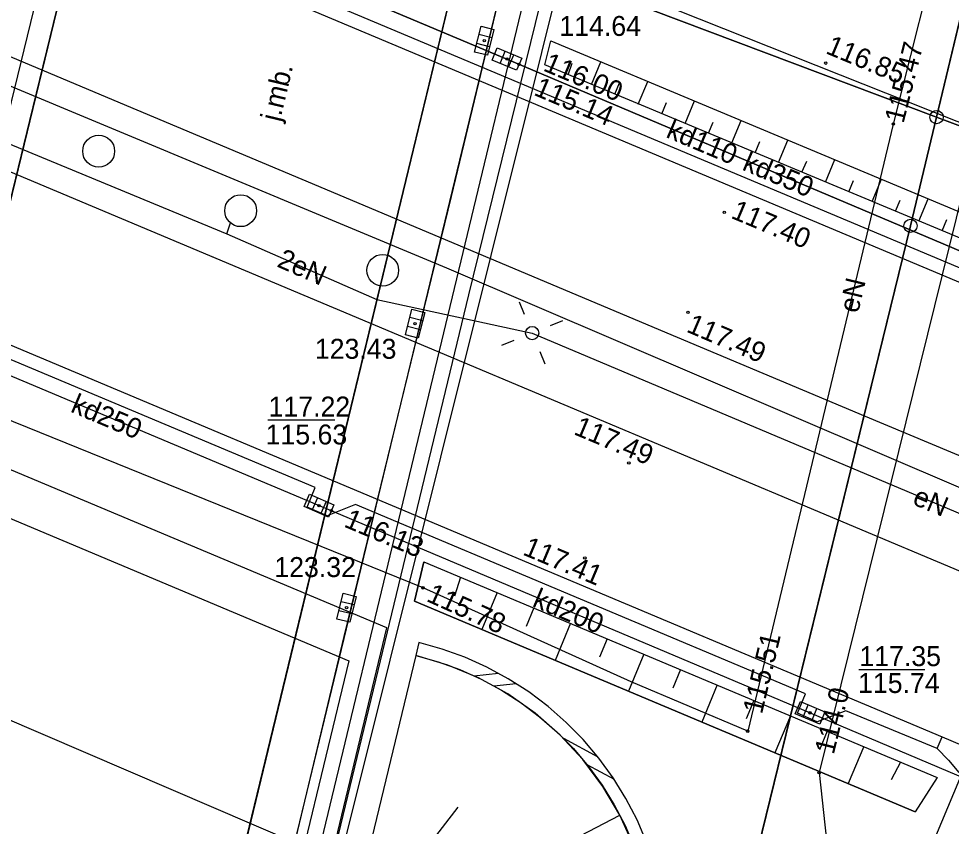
# Model space of a CAD drawing. Extents: x 6424617 to 6425697, y 5665845 to 5667190.
# Drawn here: x 6425461.6 to 6425496.67, y 5666928.18 to 5666958.55 of the extents above; entities that cross this region are included whole.
import ezdxf

# ---------------------------------------------------------------- set-up
doc = ezdxf.new("R2010")
doc.units = 0
for name, color, linetype in [('Warstwa 1', 7, 'Continuous'), ('Warstwa 10', 7, 'Continuous'), ('Warstwa 12', 7, 'Continuous'), ('Warstwa 13', 7, 'Continuous'), ('Warstwa 14', 7, 'Continuous'), ('Warstwa 15', 7, 'Continuous'), ('Warstwa 16', 7, 'Continuous'), ('Warstwa 2', 7, 'Continuous'), ('Warstwa 20', 7, 'Continuous'), ('Warstwa 21', 7, 'Continuous'), ('Warstwa 25', 7, 'Continuous'), ('Warstwa 4', 7, 'Continuous'), ('Warstwa 6', 7, 'Continuous'), ('Warstwa 8', 7, 'Continuous'), ('Warstwa 9', 7, 'Continuous')]:
    doc.layers.add(name, color=color, linetype=linetype)

msp = doc.modelspace()

# ---------------------------------------------------------------- linework, layer by layer
at = {"layer": 'Warstwa 1'}
for p, q in [((6425437.407, 5666792.342), (6425493.084, 5667022.41)), ((6425437.407, 5666792.342), (6425493.084, 5667022.41)), ((6425496.12, 5666954.85), (6425511.35, 5667018.315)), ((6425496.12, 5666954.85), (6425511.35, 5667018.315)), ((6425485.36, 5666958.9), (6425496.12, 5666954.85)), ((6425485.36, 5666958.9), (6425496.12, 5666954.85)), ((6425495.139, 5666950.762), (6425496.12, 5666954.85)), ((6425495.139, 5666950.762), (6425496.12, 5666954.85)), ((6425496.12, 5666954.85), (6425522.252, 5666945.035)), ((6425496.12, 5666954.85), (6425522.252, 5666945.035)), ((6425471.236, 5666853.116), (6425495.139, 5666950.762)), ((6425471.236, 5666853.116), (6425495.139, 5666950.762))]:
    msp.add_line(p, q, dxfattribs=at)
msp.add_lwpolyline([(6425437.93, 5666938.04), (6425438.42, 5666937.92), (6425439.31, 5666941.59), (6425439.89, 5666941.44), (6425441.5, 5666948.08), (6425474.02, 5666934.4), (6425472.29, 5666927.24), (6425472.87, 5666927.1), (6425472.03, 5666923.61), (6425472.52, 5666923.49), (6425475.45, 5666935.64), (6425458.58, 5666942.73), (6425458.34, 5666941.75), (6425456.1, 5666942.69), (6425456.34, 5666943.68), (6425440.88, 5666950.18)], close=True, dxfattribs=at)
for centre, radius in [((6425464.61, 5666953.57), 0.601), ((6425469.95, 5666951.33), 0.6), ((6425475.29, 5666949.09), 0.599)]:
    msp.add_circle(centre, radius, dxfattribs=at)
at = {"layer": 'Warstwa 10'}
for points in [[(6425485.214, 5666927.589), (6425484.855, 5666928.426), (6425484.434, 5666929.234), (6425483.955, 5666930.009), (6425483.42, 5666930.746), (6425482.831, 5666931.441), (6425482.192, 5666932.09), (6425481.507, 5666932.69), (6425480.78, 5666933.238), (6425480.013, 5666933.73), (6425479.212, 5666934.164), (6425478.381, 5666934.537), (6425477.525, 5666934.847), (6425476.648, 5666935.093), (6425476.532, 5666934.607), (6425477.372, 5666934.371), (6425478.194, 5666934.073), (6425478.991, 5666933.715), (6425479.759, 5666933.299), (6425480.494, 5666932.827), (6425481.192, 5666932.302), (6425481.849, 5666931.726), (6425482.462, 5666931.104), (6425483.026, 5666930.437), (6425483.54, 5666929.73), (6425483.999, 5666928.987), (6425484.403, 5666928.212), (6425484.747, 5666927.409)], [(6425478.72, 5666933.845), (6425479.647, 5666933.938)], [(6425479.465, 5666933.468), (6425480.306, 5666933.552)], [(6425482.086, 5666931.497), (6425483.379, 5666930.797)], [(6425482.973, 5666930.506), (6425483.992, 5666929.954)]]:
    msp.add_lwpolyline(points, dxfattribs=at)
for centre in [(6425496.12, 5666954.85), (6425496.12, 5666954.85), (6425495.139, 5666950.762), (6425495.139, 5666950.762)]:
    msp.add_circle(centre, 0.25, dxfattribs=at)
at = {"layer": 'Warstwa 12'}
for points in [[(6425454.75, 5666812.915), (6425455.753, 5666816.883), (6425457.009, 5666817.738), (6425466.513, 5666831.046), (6425477.951, 5666845.959), (6425477.163, 5666847.339), (6425475.812, 5666851.526), (6425475.173, 5666855.074), (6425474.407, 5666861.19), (6425474.538, 5666868.989), (6425475.24, 5666876.27), (6425477.752, 5666888.602), (6425479.441, 5666893.041), (6425480.828, 5666893.587), (6425484.849, 5666908.144), (6425470.76, 5666912.634), (6425469.827, 5666913.063), (6425472.078, 5666923.598), (6425472.03, 5666923.61), (6425482.03, 5666965.191), (6425489.31, 5666994.281), (6425496.49, 5667021.647)], [(6425470.675, 5666812.723), (6425472.304, 5666820.347), (6425476.107, 5666835.553), (6425479.576, 5666850.831), (6425493.276, 5666901.432), (6425493.535, 5666902.072), (6425493.16, 5666902.53), (6425486.027, 5666904.729), (6425481.07, 5666906.403), (6425469.466, 5666909.139), (6425469.101, 5666909.586), (6425469.483, 5666910.214), (6425471.98, 5666923.618), (6425472.03, 5666923.61), (6425482.03, 5666965.191), (6425489.31, 5666994.281), (6425496.49, 5667021.647)], [(6425438.44, 5666974.48), (6425442.87, 5666972.63), (6425461.54, 5666964.77), (6425479.96, 5666957.03), (6425498.41, 5666949.22), (6425503.59, 5666947.03), (6425504.05, 5666946.83)], [(6425504.05, 5666946.83), (6425503.59, 5666947.03), (6425498.41, 5666949.22), (6425479.96, 5666957.03), (6425461.54, 5666964.77), (6425442.87, 5666972.63), (6425438.44, 5666974.48)], [(6425553.71, 5666947.2), (6425549.6, 5666948.95), (6425497.24, 5666962.99), (6425496.43, 5666962.29), (6425494.49, 5666954.59), (6425489.02, 5666931.76), (6425484.64, 5666933.61), (6425476.81, 5666937.15), (6425438.84, 5666952.53), (6425435.57, 5666952.21), (6425429.97, 5666954.78), (6425402.11, 5666966.81), (6425387.27, 5666972.4), (6425380.77, 5666966.54), (6425363.64, 5666950.72), (6425363.13, 5666950.36), (6425362.37, 5666949.84), (6425357.72, 5666956.9), (6425346.14, 5666972.82)], [(6425526.974, 5666967.965), (6425526.723, 5666966.717), (6425523.453, 5666965.476), (6425499.982, 5666962.636), (6425499.521, 5666962.359), (6425497.672, 5666954.347), (6425491.703, 5666930.204), (6425491.983, 5666927.664), (6425491.536, 5666926.843), (6425491.124, 5666926.349), (6425486.048, 5666904.094), (6425485.647, 5666901.708), (6425484.933, 5666901.883), (6425464.654, 5666907.42), (6425437.078, 5666914.799)], [(6425435.28, 5666966.88), (6425435.74, 5666966.68), (6425477.69, 5666949.18), (6425500.42, 5666939.46), (6425500.88, 5666939.27)], [(6425436.62, 5666965.4), (6425444.74, 5666960.59), (6425451.33, 5666957.94), (6425469.43, 5666950.46), (6425475.07, 5666947.99), (6425480.91, 5666946.73)], [(6425429.54, 5666958.45), (6425436.02, 5666955.7), (6425454.47, 5666947.99), (6425472.9, 5666940.24)], [(6425469.43, 5666950.46), (6425469.566, 5666950.869)], [(6425480.91, 5666946.73), (6425514.86, 5666932.41), (6425528.46, 5666925.91), (6425545.47, 5666915.06), (6425553.34, 5666907.03), (6425561.44, 5666895.63), (6425564.087, 5666890.255)], [(6425472.9, 5666940.24), (6425491.36, 5666932.45)], [(6425500.88, 5666939.27), (6425494.44, 5666923.88), (6425494.89, 5666923.67), (6425515.65, 5666913.94), (6425516.1, 5666913.73), (6425516.07, 5666913.22), (6425516.03, 5666898.31)], [(6425491.36, 5666932.45), (6425509.53, 5666924.76)]]:
    msp.add_lwpolyline(points, dxfattribs=at)
at = {"layer": 'Warstwa 14'}
for p, q in [((6425473.49, 5666943.459), (6425470.977, 5666943.459)), ((6425495.68, 5666934.072), (6425493.201, 5666934.072))]:
    msp.add_line(p, q, dxfattribs=at)
for centre in [(6425479.11, 5666957.72), (6425479.96, 5666957.03), (6425480.42, 5666956.835), (6425480.42, 5666956.835), (6425494.49, 5666954.59), (6425476.51, 5666947.08), (6425472.9, 5666940.24), (6425473.361, 5666940.046), (6425476.81, 5666937.15), (6425473.93, 5666936.4), (6425491.36, 5666932.45), (6425489.02, 5666931.76), (6425491.703, 5666930.204)]:
    msp.add_circle(centre, 0.045, dxfattribs=at)
at = {"layer": 'Warstwa 16'}
msp.add_lwpolyline([(6425473.666, 5666926.849), (6425456.184, 5666934.35), (6425458.05, 5666942), (6425464.35, 5666967.83), (6425465.856, 5666974.004), (6425483.16, 5666964.87)], close=True, dxfattribs=at)
at = {"layer": 'Warstwa 2'}
for points in [[(6425482.64, 5666964.96), (6425478.52, 5666948.17), (6425472.56, 5666923.5)], [(6425569.428, 5666914.078), (6425559.167, 5666924.494), (6425550.651, 5666930.93), (6425537.233, 5666937.954), (6425528.275, 5666942.097), (6425504.759, 5666951.565), (6425481.965, 5666960.63)]]:
    msp.add_lwpolyline(points, dxfattribs=at)
msp.add_circle((6425480.91, 5666946.73), 0.25, dxfattribs=at)
at = {"layer": 'Warstwa 20'}
for points in [[(6425507.766, 5666945.809), (6425481.386, 5666956.809)], [(6425476.843, 5666938.133), (6425496.143, 5666930.021)]]:
    msp.add_lwpolyline(points, dxfattribs=at)
at = {"layer": 'Warstwa 21'}
for points in [[(6425481.612, 5666957.715), (6425506.532, 5666947.292), (6425509.043, 5666948.427)], [(6425476.484, 5666936.646), (6425495.319, 5666928.728)], [(6425477.76, 5666897.255), (6425484.833, 5666917.264), (6425484.95, 5666918.78), (6425484.717, 5666918.871), (6425485.114, 5666920.062), (6425485.382, 5666921.289), (6425485.517, 5666922.537), (6425485.519, 5666923.793), (6425485.386, 5666925.041), (6425485.122, 5666926.268), (6425484.727, 5666927.46), (6425484.208, 5666928.604), (6425483.57, 5666929.685), (6425482.82, 5666930.692), (6425481.968, 5666931.613), (6425481.021, 5666932.438), (6425479.992, 5666933.158), (6425478.892, 5666933.763), (6425477.734, 5666934.248), (6425476.531, 5666934.607)]]:
    msp.add_lwpolyline(points, dxfattribs=at)
at = {"layer": 'Warstwa 25'}
for centre in [(6425491.951, 5666956.878), (6425488.137, 5666951.268), (6425486.77, 5666947.508), (6425484.547, 5666941.847), (6425482.892, 5666938.275)]:
    msp.add_circle(centre, 0.045, dxfattribs=at)
at = {"layer": 'Warstwa 4'}
for p, q in [((6425479.395, 5666957.828), (6425478.911, 5666957.951)), ((6425479.309, 5666957.489), (6425478.825, 5666957.612)), ((6425479.703, 5666956.866), (6425479.893, 5666957.328)), ((6425480.027, 5666956.732), (6425480.217, 5666957.194)), ((6425476.796, 5666947.188), (6425476.311, 5666947.311)), ((6425476.709, 5666946.849), (6425476.224, 5666946.972)), ((6425472.841, 5666940.539), (6425472.639, 5666940.082)), ((6425473.161, 5666940.398), (6425472.959, 5666939.941)), ((6425474.214, 5666936.512), (6425473.727, 5666936.628)), ((6425474.133, 5666936.172), (6425473.646, 5666936.288)), ((6425491.101, 5666932.288), (6425491.296, 5666932.748)), ((6425491.424, 5666932.152), (6425491.619, 5666932.612))]:
    msp.add_line(p, q, dxfattribs=at)
for points in [[(6425479.475, 5666958.143), (6425479.229, 5666957.174), (6425478.745, 5666957.297), (6425478.991, 5666958.266)], [(6425480.327, 5666956.608), (6425479.402, 5666956.989), (6425479.593, 5666957.452), (6425480.518, 5666957.071)], [(6425476.876, 5666947.502), (6425476.628, 5666946.534), (6425476.144, 5666946.658), (6425476.392, 5666947.626)], [(6425472.543, 5666940.671), (6425473.458, 5666940.267), (6425473.257, 5666939.809), (6425472.342, 5666940.213)], [(6425474.289, 5666936.828), (6425474.057, 5666935.856), (6425473.571, 5666935.972), (6425473.803, 5666936.944)], [(6425491.723, 5666932.025), (6425490.802, 5666932.414), (6425490.997, 5666932.875), (6425491.918, 5666932.486)]]:
    msp.add_lwpolyline(points, close=True, dxfattribs=at)
for points in [[(6425480.626, 5666947.424), (6425480.437, 5666947.887)], [(6425481.604, 5666947.014), (6425482.067, 5666947.203)], [(6425480.216, 5666946.446), (6425479.753, 5666946.257)], [(6425481.194, 5666946.036), (6425481.383, 5666945.573)]]:
    msp.add_lwpolyline(points, dxfattribs=at)
at = {"layer": 'Warstwa 6'}
for points in [[(6425493.084, 5667022.41), (6425437.407, 5666792.342), (6425392.62, 5666819.33), (6425356.96, 5666840.82), (6425364.08, 5666857.99), (6425325.81, 5666937.38), (6425352.9, 5666950.36), (6425340.11, 5666976.98), (6425316.39, 5667007.21), (6425286.52, 5667014.65), (6425266.76, 5667059.81), (6425269.791, 5667072.474)], [(6425493.084, 5667022.41), (6425437.407, 5666792.342), (6425454.155, 5666782.149), (6425471.236, 5666853.116), (6425495.139, 5666950.762), (6425496.12, 5666954.85), (6425485.36, 5666958.9), (6425501.348, 5667020.558)], [(6425465.459, 5666899.926), (6425466.149, 5666902.821), (6425466.855, 5666905.711), (6425467.577, 5666908.598), (6425468.314, 5666911.481), (6425468.652, 5666911.404), (6425468.837, 5666912.201), (6425468.584, 5666912.605), (6425468.79, 5666914.12), (6425470.47, 5666921.31), (6425471.24, 5666921.52), (6425471.39, 5666922.11), (6425470.8, 5666922.6), (6425471.1, 5666923.83), (6425473.84, 5666935.32), (6425477.88, 5666951.86), (6425480.16, 5666961.37), (6425481.19, 5666965.36), (6425488.69, 5666995.25), (6425495.536, 5667021.861)], [(6425511.35, 5667018.315), (6425496.12, 5666954.85), (6425485.36, 5666958.9), (6425501.348, 5667020.558)], [(6425511.35, 5667018.315), (6425496.12, 5666954.85), (6425522.252, 5666945.035), (6425525.198, 5666957.05), (6425527.303, 5666965.745), (6425538.589, 5667012.208)], [(6425467.43, 5666976.75), (6425465.18, 5666967.73), (6425462.01, 5666954.72), (6425458.83, 5666941.66), (6425456.77, 5666933.14)], [(6425445.646, 5666970.749), (6425497.767, 5666948.85), (6425498.132, 5666949.624), (6425498.866, 5666949.291), (6425499.296, 5666948.203), (6425507.378, 5666944.806), (6425507.179, 5666944.349)], [(6425474.6, 5666748.65), (6425522.252, 5666945.035), (6425496.12, 5666954.85), (6425495.139, 5666950.762), (6425471.236, 5666853.116), (6425454.155, 5666782.149)], [(6425496.14, 5666931.11), (6425492.711, 5666932.526), (6425491.633, 5666932.106), (6425490.889, 5666932.439), (6425491.192, 5666933.164), (6425474.265, 5666940.282), (6425473.197, 5666939.861), (6425472.453, 5666940.185), (6425472.746, 5666940.92), (6425455.819, 5666948.027)]]:
    msp.add_lwpolyline(points, dxfattribs=at)
at = {"layer": 'Warstwa 8'}
for p, q in [((6425456.98, 5666934.008), (6425466.642, 5666973.589)), ((6425401.285, 5666971.5), (6425496.325, 5666931.551)), ((6425445.458, 5666970.292), (6425507.179, 5666944.349)), ((6425471.991, 5666927.568), (6425480.16, 5666961.37)), ((6425443.04, 5666960.462), (6425476.973, 5666946.195)), ((6425458.123, 5666958.452), (6425465.184, 5666955.484)), ((6425465.184, 5666955.484), (6425472.246, 5666952.516)), ((6425472.246, 5666952.516), (6425479.307, 5666949.548)), ((6425479.307, 5666949.548), (6425486.368, 5666946.579)), ((6425486.368, 5666946.579), (6425493.429, 5666943.61)), ((6425476.973, 5666946.195), (6425506.081, 5666933.955)), ((6425493.429, 5666943.61), (6425500.49, 5666940.641)), ((6425496.14, 5666931.11), (6425496.325, 5666931.551)), ((6425496.325, 5666931.551), (6425508.882, 5666926.212)), ((6425496.325, 5666931.551), (6425508.882, 5666926.212)), ((6425496.14, 5666931.11), (6425496.565, 5666930.675)), ((6425496.565, 5666930.675), (6425496.956, 5666930.21))]:
    msp.add_line(p, q, dxfattribs=at)
msp.add_lwpolyline([(6425497.672, 5666954.347), (6425491.703, 5666930.204), (6425491.983, 5666927.664), (6425491.536, 5666926.843), (6425491.124, 5666926.349), (6425486.048, 5666904.094)], dxfattribs=at)
at = {"layer": 'Warstwa 9'}
for p, q in [((6425481.386, 5666956.809), (6425481.612, 5666957.715)), ((6425482.266, 5666956.443), (6425482.41, 5666956.882)), ((6425483.145, 5666956.076), (6425483.499, 5666956.926)), ((6425484.024, 5666955.709), (6425484.201, 5666956.134)), ((6425484.903, 5666955.342), (6425485.257, 5666956.19)), ((6425485.783, 5666954.976), (6425485.959, 5666955.399)), ((6425486.662, 5666954.609), (6425487.015, 5666955.455)), ((6425487.542, 5666954.242), (6425487.718, 5666954.665)), ((6425488.421, 5666953.876), (6425488.773, 5666954.72)), ((6425489.3, 5666953.509), (6425489.476, 5666953.931)), ((6425490.179, 5666953.142), (6425490.531, 5666953.985)), ((6425491.058, 5666952.776), (6425491.234, 5666953.196)), ((6425491.938, 5666952.409), (6425492.289, 5666953.249)), ((6425492.818, 5666952.042), (6425492.993, 5666952.462)), ((6425493.697, 5666951.676), (6425494.047, 5666952.514)), ((6425494.576, 5666951.309), (6425494.751, 5666951.728)), ((6425495.455, 5666950.942), (6425495.804, 5666951.779)), ((6425496.334, 5666950.576), (6425496.509, 5666950.994)), ((6425476.843, 5666938.133), (6425476.484, 5666936.646)), ((6425478.222, 5666937.553), (6425477.986, 5666936.834)), ((6425479.6, 5666936.974), (6425479.015, 5666935.582)), ((6425480.978, 5666936.394), (6425480.686, 5666935.698)), ((6425482.357, 5666935.815), (6425481.772, 5666934.423)), ((6425483.736, 5666935.235), (6425483.443, 5666934.54)), ((6425485.114, 5666934.656), (6425484.529, 5666933.264)), ((6425486.493, 5666934.077), (6425486.2, 5666933.381)), ((6425487.872, 5666933.498), (6425487.286, 5666932.105)), ((6425489.25, 5666932.918), (6425488.958, 5666932.222)), ((6425490.629, 5666932.339), (6425490.043, 5666930.946)), ((6425492.008, 5666931.76), (6425491.714, 5666931.063)), ((6425493.386, 5666931.18), (6425492.8, 5666929.787)), ((6425494.764, 5666930.6), (6425494.412, 5666929.929)), ((6425496.143, 5666930.021), (6425495.319, 5666928.728)), ((6425474.348, 5666924.01), (6425478.123, 5666928.899)), ((6425474.67, 5666923.64), (6425484.208, 5666928.605))]:
    msp.add_line(p, q, dxfattribs=at)
for points in [[(6425509.043, 5666948.427), (6425508.524, 5666947.356), (6425508.336, 5666946.899), (6425507.766, 5666945.809), (6425481.386, 5666956.809), (6425481.612, 5666957.715), (6425506.532, 5666947.292)], [(6425476.843, 5666938.133), (6425496.143, 5666930.021), (6425495.319, 5666928.728), (6425476.484, 5666936.646)]]:
    msp.add_lwpolyline(points, close=True, dxfattribs=at)
msp.add_lwpolyline([(6425484.727, 5666927.46), (6425484.208, 5666928.604), (6425483.57, 5666929.685), (6425482.82, 5666930.692), (6425481.968, 5666931.613), (6425481.021, 5666932.438), (6425479.992, 5666933.158), (6425478.892, 5666933.763), (6425477.734, 5666934.248), (6425476.531, 5666934.607), (6425474.02, 5666924.16)], dxfattribs=at)

# ---------------------------------------------------------------- texts
at = {"layer": 'Warstwa 13'}
for s, rotation, p in [('kd110', 337.0596, (6425485.905, 5666954.107)), ('kd350', 337.0596, (6425488.771, 5666952.881)), ('2eN', 336.3491, (6425471.277, 5666949.242)), ('eN', 76.5242, (6425493.164, 5666947.446)), ('kd250', 337.1914, (6425463.514, 5666943.779)), ('eN', 337.1284, (6425495.171, 5666940.308)), ('kd200', 337.1226, (6425480.878, 5666936.466))]:
    msp.add_text(s, height=0.75, rotation=rotation, dxfattribs=at).set_placement(p)
at = {"layer": 'Warstwa 14'}
for s, p in [('114.64', (6425481.935, 5666957.902)), ('115.63', (6425470.888, 5666942.54)), ('115.74', (6425493.168, 5666933.196))]:
    msp.add_text(s, height=0.75, dxfattribs=at).set_placement(p)
for s, rotation, p in [('115.47', 75.8596, (6425494.875, 5666954.585)), ('116.00', 337.0596, (6425481.288, 5666956.61)), ('115.14', 337.0596, (6425480.934, 5666955.694)), ('116.13', 337.1226, (6425473.795, 5666939.462)), ('115.78', 335.6731, (6425476.898, 5666936.664)), ('115.51', 76.5242, (6425489.552, 5666932.374)), ('114.0', 76.1117, (6425492.25, 5666930.853))]:
    msp.add_text(s, height=0.75, rotation=rotation, dxfattribs=at).set_placement(p)
at = {"layer": 'Warstwa 15'}
for s, p in [('123.43', (6425472.74, 5666945.763)), ('117.22', (6425471, 5666943.59)), ('123.32', (6425471.216, 5666937.556)), ('117.35', (6425493.218, 5666934.207))]:
    msp.add_text(s, height=0.75, dxfattribs=at).set_placement(p)
at = {"layer": 'Warstwa 25'}
for s, rotation, p in [('116.85', 337.3003, (6425491.913, 5666957.26)), ('117.40', 337.2029, (6425488.349, 5666951.069)), ('117.49', 336.8476, (6425486.674, 5666946.792)), ('117.49', 337.1914, (6425482.437, 5666942.937)), ('117.41', 337.2029, (6425480.522, 5666938.408))]:
    msp.add_text(s, height=0.75, rotation=rotation, dxfattribs=at).set_placement(p)
at = {"layer": 'Warstwa 8'}
msp.add_text('j.mb.', height=0.75, rotation=76.5185, dxfattribs=at).set_placement((6425471.42, 5666954.647))

doc.saveas('drawing.dxf')
